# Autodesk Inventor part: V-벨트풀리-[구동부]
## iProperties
Company: 한국ATC센터
Created: 2014-10
Part Number: V-벨트풀리-[구동부]
Document SubType Name: Modeling
Designer: 한국ATC센터
Density: 7.86 g/cm^3
Material: 강, 연강
Mass: 1515.01 g
Surface Area: 468.111 cm^2
Volume: 192.75 cm^3
Author: KYOUNG IL JANG
